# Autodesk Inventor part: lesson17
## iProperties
Author: Administrator
Created: 2001-01
Part Number: lesson17
Document SubType Name: Modeling
Designer: Administrator
Control State: 0
Master: False
Checked Out: False
PropertySet Name: Design Tracking Control
Shininess: 0.0
PropertySet Name: _Private Model Information
Density: 0.0
Volumn: 0.0
Area: 0.0
PropertySet Name: Model Information
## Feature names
1. Extrusion1
2. Extrusion2
3. Hole1
4. Fillet1
5. Extrusion3
6. Hole2
7. Rectangular Pattern1
8. Fillet2
9. Fillet3
10. Fillet4
11. Fillet5
